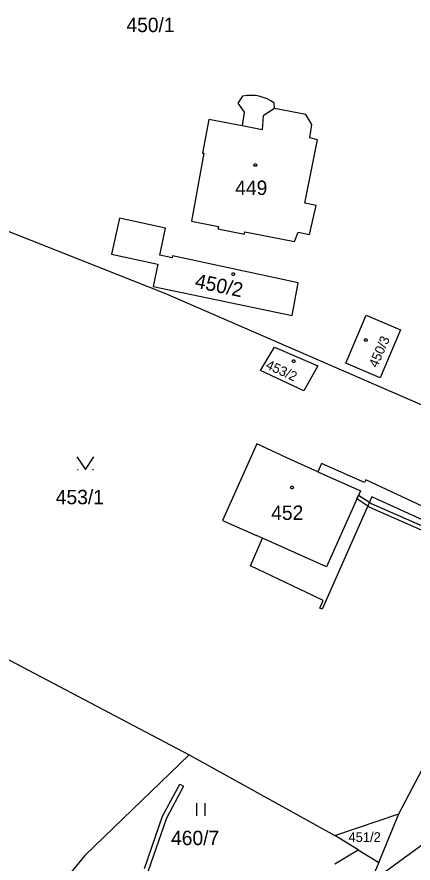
# Model space of a CAD drawing. Extents: x -759699 to -757730, y -1172308 to -1170857.
# Drawn here: x -759282.5 to -759235.7, y -1171675.5 to -1171575.6 of the extents above; entities that cross this region are included whole.
import ezdxf

# ---------------------------------------------------------------- set-up
doc = ezdxf.new("R2010")
doc.units = 0
for name, color, linetype in [('Vrstva 1', 7, 'Continuous'), ('Vrstva 12', 7, 'Continuous'), ('Vrstva 13', 7, 'Continuous'), ('Vrstva 2', 7, 'Continuous'), ('Vrstva 3', 7, 'Continuous'), ('Vrstva 4', 7, 'Continuous'), ('Vrstva 5', 7, 'Continuous')]:
    doc.layers.add(name, color=color, linetype=linetype)

msp = doc.modelspace()

# ---------------------------------------------------------------- linework, layer by layer
at = {"layer": 'Vrstva 1'}
for p, q in [((-759255.87, -1171584.99), (-759256.44, -1171585.83)), ((-759256.44, -1171585.83), (-759255.68, -1171586.87)), ((-759252.12, -1171586.45), (-759252.13, -1171585.8)), ((-759255.68, -1171586.87), (-759255.94, -1171588.49)), ((-759248.41, -1171587.17), (-759252.12, -1171586.45)), ((-759247.69, -1171588.32), (-759248.41, -1171587.17)), ((-759259.86, -1171587.73), (-759260.59, -1171591.7)), ((-759255.94, -1171588.49), (-759259.86, -1171587.73)), ((-759247.93, -1171589.91), (-759247.69, -1171588.32)), ((-759248.53, -1171597.61), (-759247.04, -1171590.14)), ((-759247.04, -1171590.14), (-759247.93, -1171589.91)), ((-759260.44, -1171591.73), (-759261.9, -1171599.74)), ((-759260.59, -1171591.7), (-759260.44, -1171591.73)), ((-759264.92, -1171608.32), (-759303.12, -1171593.25)), ((-759247.19, -1171597.88), (-759248.53, -1171597.61)), ((-759247.99, -1171601.32), (-759247.19, -1171597.88)), ((-759270.42, -1171599.4), (-759271.33, -1171603.65)), ((-759264.96, -1171600.57), (-759270.42, -1171599.4)), ((-759261.9, -1171599.74), (-759258.73, -1171600.37)), ((-759265.65, -1171603.77), (-759264.96, -1171600.57)), ((-759258.73, -1171600.37), (-759258.79, -1171600.66)), ((-759258.79, -1171600.66), (-759255.64, -1171601.29)), ((-759255.64, -1171601.29), (-759255.59, -1171601)), ((-759255.59, -1171601), (-759249.73, -1171602.16)), ((-759249.73, -1171602.16), (-759249.31, -1171601.03)), ((-759249.31, -1171601.03), (-759247.99, -1171601.32)), ((-759271.33, -1171603.65), (-759265.87, -1171604.83)), ((-759264.2, -1171604.08), (-759265.65, -1171603.77)), ((-759264.15, -1171603.84), (-759264.2, -1171604.08)), ((-759249.31, -1171607.02), (-759264.15, -1171603.84)), ((-759265.87, -1171604.83), (-759266.44, -1171607.46)), ((-759250.02, -1171610.89), (-759249.31, -1171607.02)), ((-759266.44, -1171607.46), (-759250.02, -1171610.89)), ((-759223.87, -1171626.2), (-759264.92, -1171608.32)), ((-759243.68, -1171616.52), (-759241.27, -1171610.85)), ((-759241.27, -1171610.85), (-759237.23, -1171612.57)), ((-759237.23, -1171612.57), (-759239.64, -1171618.24)), ((-759253.74, -1171617.38), (-759252.12, -1171614.61)), ((-759252.12, -1171614.61), (-759246.98, -1171616.83)), ((-759246.98, -1171616.83), (-759248.63, -1171619.79)), ((-759239.64, -1171618.24), (-759243.68, -1171616.52)), ((-759248.63, -1171619.79), (-759253.74, -1171617.38)), ((-759254.2, -1171626.05), (-759258.25, -1171635.09)), ((-759250.15, -1171627.92), (-759254.2, -1171626.05)), ((-759247, -1171629.34), (-759250.15, -1171627.92)), ((-759246.55, -1171628.34), (-759247, -1171629.34)), ((-759241.47, -1171630.61), (-759246.55, -1171628.34)), ((-759241.31, -1171630.28), (-759241.47, -1171630.61)), ((-759222.99, -1171638.88), (-759241.31, -1171630.28)), ((-759240.61, -1171632.28), (-759246.49, -1171645.57)), ((-759234.56, -1171635.04), (-759240.61, -1171632.28)), ((-759258.25, -1171635.09), (-759254.21, -1171636.86)), ((-759254.92, -1171640.44), (-759253.52, -1171637.17)), ((-759253.52, -1171637.17), (-759254.21, -1171636.86)), ((-759247.51, -1171643.97), (-759254.92, -1171640.44)), ((-759297.81, -1171644), (-759262.18, -1171662.76)), ((-759246.36, -1171644.54), (-759247.51, -1171643.97)), ((-759246.76, -1171645.45), (-759246.36, -1171644.54)), ((-759246.49, -1171645.57), (-759246.76, -1171645.45)), ((-759262.18, -1171662.76), (-759274.51, -1171674.64)), ((-759262.18, -1171662.76), (-759245, -1171672.28)), ((-759237.43, -1171669.72), (-759234.63, -1171664.42)), ((-759245, -1171672.28), (-759237.43, -1171669.72)), ((-759239.78, -1171675.47), (-759237.43, -1171669.72)), ((-759238.96, -1171676.49), (-759231.42, -1171670.95)), ((-759242.21, -1171673.99), (-759245, -1171672.28)), ((-759244.98, -1171675.61), (-759242.21, -1171673.99)), ((-759242.21, -1171673.99), (-759239.78, -1171675.47)), ((-759274.51, -1171674.64), (-759276.45, -1171677.04)), ((-759239.78, -1171675.47), (-759240.6, -1171677.37))]:
    msp.add_line(p, q, dxfattribs=at)
msp.add_arc((-759254.915, -1171589.621), 4.729, 53.91252, 101.64699, dxfattribs=at)
at = {"layer": 'Vrstva 12'}
for p, q in [((-759253.43, -1171587.3), (-759253.58, -1171588.95)), ((-759252.12, -1171586.45), (-759253.43, -1171587.3)), ((-759248.41, -1171587.17), (-759252.12, -1171586.45)), ((-759247.69, -1171588.32), (-759248.41, -1171587.17)), ((-759259.86, -1171587.73), (-759260.59, -1171591.7)), ((-759255.94, -1171588.49), (-759259.86, -1171587.73)), ((-759247.93, -1171589.91), (-759247.69, -1171588.32)), ((-759253.58, -1171588.95), (-759255.94, -1171588.49)), ((-759248.53, -1171597.61), (-759247.04, -1171590.14)), ((-759247.04, -1171590.14), (-759247.93, -1171589.91)), ((-759260.44, -1171591.73), (-759261.9, -1171599.74)), ((-759260.59, -1171591.7), (-759260.44, -1171591.73)), ((-759247.19, -1171597.88), (-759248.53, -1171597.61)), ((-759247.99, -1171601.32), (-759247.19, -1171597.88)), ((-759270.42, -1171599.4), (-759271.33, -1171603.65)), ((-759264.96, -1171600.57), (-759270.42, -1171599.4)), ((-759261.9, -1171599.74), (-759258.73, -1171600.37)), ((-759265.65, -1171603.77), (-759264.96, -1171600.57)), ((-759258.73, -1171600.37), (-759258.79, -1171600.66)), ((-759258.79, -1171600.66), (-759255.64, -1171601.29)), ((-759255.64, -1171601.29), (-759255.59, -1171601)), ((-759255.59, -1171601), (-759249.73, -1171602.16)), ((-759249.73, -1171602.16), (-759249.31, -1171601.03)), ((-759249.31, -1171601.03), (-759247.99, -1171601.32)), ((-759271.33, -1171603.65), (-759265.87, -1171604.83)), ((-759264.2, -1171604.08), (-759265.65, -1171603.77)), ((-759264.15, -1171603.84), (-759264.2, -1171604.08)), ((-759249.31, -1171607.02), (-759264.15, -1171603.84)), ((-759265.87, -1171604.83), (-759266.44, -1171607.46)), ((-759250.02, -1171610.89), (-759249.31, -1171607.02)), ((-759266.44, -1171607.46), (-759250.02, -1171610.89)), ((-759243.68, -1171616.52), (-759241.27, -1171610.85)), ((-759241.27, -1171610.85), (-759237.23, -1171612.57)), ((-759237.23, -1171612.57), (-759239.64, -1171618.24)), ((-759253.74, -1171617.38), (-759252.12, -1171614.61)), ((-759252.12, -1171614.61), (-759246.98, -1171616.83)), ((-759246.98, -1171616.83), (-759248.63, -1171619.79)), ((-759239.64, -1171618.24), (-759243.68, -1171616.52)), ((-759248.63, -1171619.79), (-759253.74, -1171617.38)), ((-759254.2, -1171626.05), (-759258.25, -1171635.09)), ((-759250.15, -1171627.92), (-759254.2, -1171626.05)), ((-759247, -1171629.34), (-759250.15, -1171627.92)), ((-759247, -1171629.34), (-759241.97, -1171631.6)), ((-759241.97, -1171631.6), (-759245.97, -1171640.56)), ((-759258.25, -1171635.09), (-759254.21, -1171636.86)), ((-759253.52, -1171637.17), (-759254.21, -1171636.86)), ((-759245.97, -1171640.56), (-759253.52, -1171637.17))]:
    msp.add_line(p, q, dxfattribs=at)
at = {"layer": 'Vrstva 13'}
for p, q in [((-759242.39, -1171632.55), (-759242.19, -1171632.09)), ((-759242.19, -1171632.09), (-759240.9, -1171632.94)), ((-759241.1, -1171633.4), (-759242.39, -1171632.55)), ((-759240.9, -1171632.94), (-759240.68, -1171633.08)), ((-759240.68, -1171633.08), (-759227.4, -1171638.95)), ((-759240.92, -1171633.52), (-759241.1, -1171633.4)), ((-759227.58, -1171639.41), (-759240.92, -1171633.52)), ((-759265.31, -1171670.01), (-759263.3, -1171666.23)), ((-759263.3, -1171666.23), (-759262.85, -1171666.47)), ((-759262.85, -1171666.47), (-759264.85, -1171670.23)), ((-759267.46, -1171676.19), (-759265.31, -1171670.01)), ((-759264.85, -1171670.23), (-759267.07, -1171676.58))]:
    msp.add_line(p, q, dxfattribs=at)
at = {"layer": 'Vrstva 3'}
for p, q in [((-759275.38, -1171629.06), (-759275.28, -1171629.06)), ((-759273.58, -1171629.06), (-759273.48, -1171629.06)), ((-759261.3, -1171668.46), (-759261.3, -1171669.96)), ((-759260.3, -1171669.96), (-759260.3, -1171668.46))]:
    msp.add_line(p, q, dxfattribs=at)
msp.add_lwpolyline([(-759275.43, -1171627.56), (-759274.43, -1171629.06), (-759273.43, -1171627.56)], dxfattribs=at)
at = {"layer": 'Vrstva 4'}
for p, q in [((-759253.43, -1171587.3), (-759253.58, -1171588.95)), ((-759252.12, -1171586.45), (-759253.43, -1171587.3)), ((-759253.58, -1171588.95), (-759255.94, -1171588.49)), ((-759247, -1171629.34), (-759241.97, -1171631.6)), ((-759241.97, -1171631.6), (-759245.97, -1171640.56)), ((-759245.97, -1171640.56), (-759253.52, -1171637.17))]:
    msp.add_line(p, q, dxfattribs=at)
at = {"layer": 'Vrstva 5'}
for points in [[(-759254.27, -1171592.97), (-759254.18, -1171593.12), (-759254.27, -1171593.27), (-759254.45, -1171593.27), (-759254.54, -1171593.12), (-759254.45, -1171592.97)], [(-759256.88, -1171605.86), (-759256.79, -1171606.01), (-759256.88, -1171606.16), (-759257.06, -1171606.16), (-759257.15, -1171606.01), (-759257.06, -1171605.86)], [(-759241.23, -1171613.62), (-759241.14, -1171613.77), (-759241.23, -1171613.92), (-759241.41, -1171613.92), (-759241.5, -1171613.77), (-759241.41, -1171613.62)], [(-759249.75, -1171616.12), (-759249.66, -1171616.27), (-759249.75, -1171616.42), (-759249.93, -1171616.42), (-759250.02, -1171616.27), (-759249.93, -1171616.12)], [(-759249.96, -1171631.04), (-759249.87, -1171631.19), (-759249.96, -1171631.34), (-759250.14, -1171631.34), (-759250.23, -1171631.19), (-759250.14, -1171631.04)]]:
    msp.add_lwpolyline(points, close=True, dxfattribs=at)

# ---------------------------------------------------------------- texts
at = {"layer": 'Vrstva 2'}
for s, height, p in [('450/1', 1.7, (-759269.589, -1171577.42)), ('449', 1.7, (-759256.744, -1171596.65)), ('453/1', 1.7, (-759277.929, -1171633.17)), ('452', 1.7, (-759252.495, -1171635.02)), ('460/7', 1.7, (-759264.32, -1171673.42)), ('451/2', 1.14, (-759243.37, -1171673.04))]:
    msp.add_text(s, height=height, dxfattribs=at).set_placement(p)
for s, height, rotation, p in [('450/2', 1.7, 348.12916, (-759261.594, -1171607.573)), ('450/3', 1.14, 66.29122, (-759239.989, -1171617.127)), ('453/2', 1.14, 335.2949, (-759253.238, -1171617.1))]:
    msp.add_text(s, height=height, rotation=rotation, dxfattribs=at).set_placement(p)

doc.saveas('drawing.dxf')
